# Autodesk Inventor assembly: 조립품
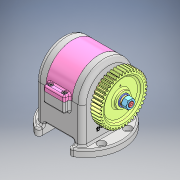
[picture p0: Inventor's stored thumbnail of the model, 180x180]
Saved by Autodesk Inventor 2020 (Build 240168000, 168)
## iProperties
Created: 2025-05
Part Number: 조립품
Document SubType Name: Assembly
Designer: 1강의실14
Author: 1강의실14
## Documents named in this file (21)
- C:\Users\1강의실14\Desktop\650503V1003\조립품.iam
- C:\Users\1강의실14\Desktop\650503V1003\본체.ipt
- C:\Users\1강의실14\Desktop\650503V1003\링크.ipt
- C:\Users\1강의실14\Desktop\650503V1003\부시 커버.ipt
- C:\Users\1강의실14\Desktop\650503V1003\스퍼 기어.ipt
- C:\Users\1강의실14\Desktop\650503V1003\스프링 와셔 M10.ipt
- C:\Users\1강의실14\Desktop\650503V1003\앞커버.ipt
- C:\Users\1강의실14\Desktop\650503V1003\오일레스 부시 20 15.ipt
- C:\Users\1강의실14\Desktop\650503V1003\오일실 20 32 5.ipt
- C:\Users\1강의실14\Desktop\650503V1003\윗커버.ipt
- C:\Users\1강의실14\Desktop\650503V1003\육각 너트 M10x1.ipt
- C:\Users\1강의실14\Desktop\650503V1003\육각 소켓 머리 볼트 M4x10.ipt
- C:\Users\1강의실14\Desktop\650503V1003\칼라.ipt
- C:\Users\1강의실14\Desktop\650503V1003\펀치.ipt
- C:\Users\1강의실14\Desktop\650503V1003\편심축.ipt
- C:\Users\1강의실14\Desktop\650503V1003\평와셔 M10.ipt
- C:\Users\1강의실14\Desktop\650503V1003\평행키 5x5x12.ipt
- C:\Users\1강의실14\Desktop\650503V1003\핀.ipt
- C:\Users\1강의실14\Desktop\650503V1003\E형 멈춤링 10-8.ipt
- C:\Users\1강의실14\Desktop\650503V1003\깊은 홈 볼 베어링 6904.ipt
- C:\Users\1강의실14\Desktop\650503V1003\뒷커버.ipt
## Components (2 placed, 2 different names)
1. 핀:1 — 각도:9, 각도:10
2. E형 멈춤링 10-8:1 — 각도:9
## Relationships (2: Angle 2)
- 각도:9 [Angle]: 핀:1 ↔ E형 멈춤링 10-8:1
- 각도:10 [Angle]: 핀:1
